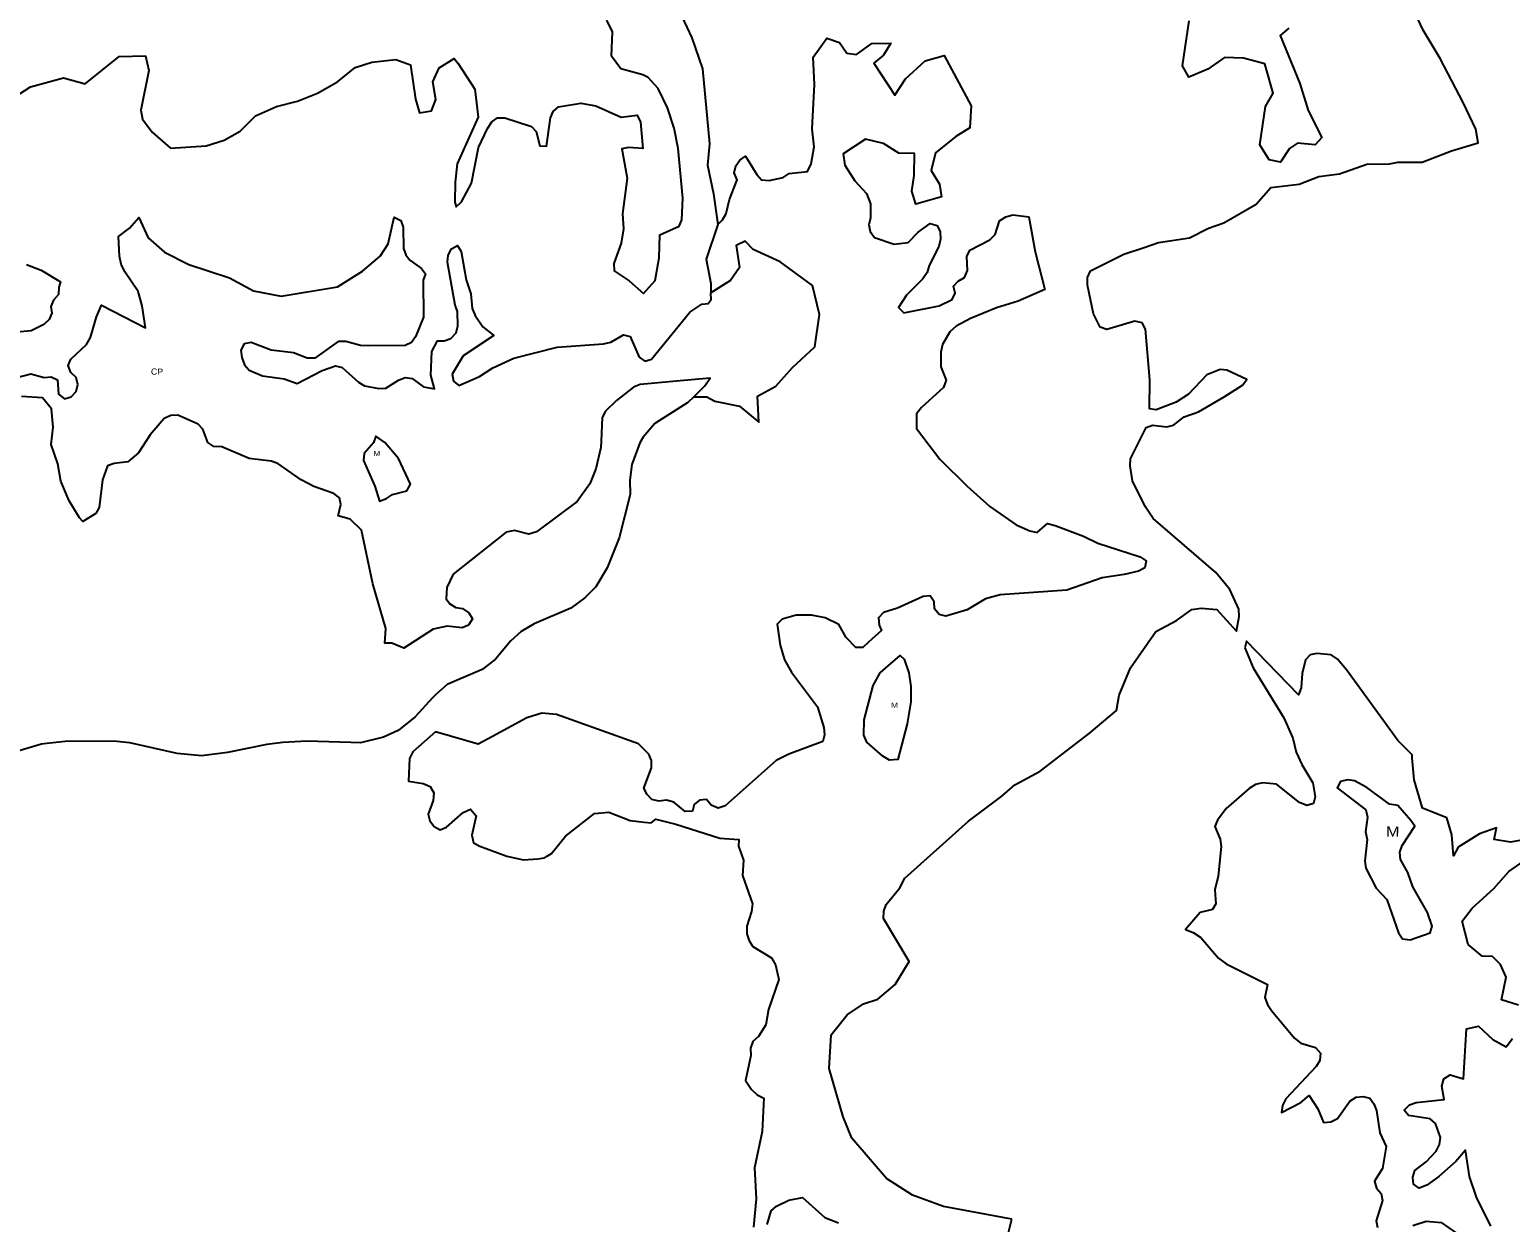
# Model space of a CAD drawing. Extents: x 713589 to 726391, y 7177764 to 7191819.
# Drawn here: x 722384 to 723901, y 7187990 to 7189212 of the extents above; entities that cross this region are included whole.
import ezdxf
from ezdxf.enums import TextEntityAlignment as Align

# ---------------------------------------------------------------- set-up
doc = ezdxf.new("R2010")
doc.units = 0
doc.header["$LTSCALE"] = 2.6
doc.layers.add('63', color=7, linetype='Continuous', lineweight=25)

msp = doc.modelspace()

# ---------------------------------------------------------------- linework, layer by layer
at = {"layer": '63'}
for points in [[(723389.91, 7187993.49), (723320.07, 7188006.34), (723288.31, 7188018.13), (723261.46, 7188035.17), (723226.1, 7188076.44), (723217.26, 7188098.38), (723202.86, 7188147.84), (723204.84, 7188182.22), (723221.22, 7188202.85), (723237.92, 7188213.98), (723252.66, 7188218.89), (723270.35, 7188233.95), (723284.89, 7188257.5), (723258.57, 7188301.42), (723258.9, 7188308.95), (723261.19, 7188315.83), (723275.28, 7188332.85), (723280.22, 7188342.71), (723345.7, 7188401.28), (723377.07, 7188424.8), (723379.77, 7188426.82), (723393.06, 7188438.48), (723419.07, 7188452.36), (723469.19, 7188490.99), (723497.03, 7188514.56), (723499.98, 7188530.28), (723511.45, 7188558.11), (723537.33, 7188595.44), (723558.62, 7188606.57), (723574.4, 7188617.83), (723583.84, 7188619.34), (723599.85, 7188618.12), (723619.83, 7188596.1), (723620, 7188595.93), (723622.98, 7188610.8), (723622.65, 7188618.39), (723613.41, 7188638.54), (723598.88, 7188655.72), (723534.82, 7188711.21), (723526.57, 7188723.43), (723513.7, 7188749.86), (723511.06, 7188765.05), (723511.39, 7188772.31), (723527.58, 7188804.34), (723534.18, 7188806.65), (723548.71, 7188805), (723555.65, 7188806.65), (723566.55, 7188815.23), (723581.08, 7188820.51), (723607.5, 7188835.7), (723626.33, 7188847.92), (723630.62, 7188853.53), (723610.15, 7188863.11), (723603.22, 7188863.77), (723589.68, 7188858.49), (723570.85, 7188838.68), (723558.3, 7188830.43), (723537.82, 7188822.51), (723530.88, 7188823.5), (723531.22, 7188853.22), (723526.94, 7188905.07), (723523.31, 7188911.67), (723516.04, 7188913.33), (723487.31, 7188904.75), (723480.37, 7188907.06), (723473.77, 7188920.93), (723467.5, 7188950.33), (723467.51, 7188957.92), (723470.48, 7188964.86), (723504.83, 7188982.02), (723525.64, 7188988.95), (723540.17, 7188993.9), (723571.87, 7188998.52), (723591.36, 7189008.42), (723607.21, 7189014.03), (723640.24, 7189033.18), (723655.44, 7189050.35), (723684.17, 7189053.65), (723704.31, 7189061.57), (723725.78, 7189064.2), (723753.52, 7189074.11), (723776.97, 7189074.43), (723785.56, 7189076.08), (723810.19, 7189076.2), (723840.38, 7189087.74), (723867.83, 7189095.87), (723865.48, 7189109.93), (723852.55, 7189136.7), (723828.72, 7189182.36), (723811.35, 7189211.55), (723795.36, 7189245.87)], [(723051.77, 7189225.54), (723061.97, 7189203.57), (723073.17, 7189171.66), (723080.1, 7189094.88), (723078.31, 7189072.96), (723084.37, 7189043.81), (723088.89, 7189012.51)], [(722980.78, 7189209.68), (722975, 7189221.69)], [(723673.6, 7189213.4), (723665.01, 7189205.89), (723685.06, 7189156.82), (723693.52, 7189129.03), (723707.48, 7189101.57), (723700.6, 7189094.06), (723682.78, 7189095.49), (723674.54, 7189090.04), (723665.24, 7189076.36), (723653.6, 7189078.46), (723644.06, 7189093.91), (723649.68, 7189133.3), (723657.61, 7189146.98), (723649.15, 7189176.82), (723627.23, 7189182.72), (723607.71, 7189183.48), (723590.87, 7189171.54), (723571.31, 7189163.39), (723564.84, 7189174.72), (723571.51, 7189220.95)], [(722351.49, 7189132.15), (722384.46, 7189153.29), (722418.41, 7189162.42), (722440.67, 7189156.51), (722475.37, 7189184.49), (722502.38, 7189185.01), (722505.71, 7189170.22), (722497.68, 7189129.47), (722499.21, 7189120.12), (722509.25, 7189106.82), (722528.04, 7189090.65), (722564.72, 7189092.92), (722582.9, 7189098.68), (722599.38, 7189107.87), (722615.2, 7189123.58), (722636.48, 7189133.1), (722658.08, 7189138.85), (722678.67, 7189147), (722699.27, 7189158.58), (722717.14, 7189173.25), (722734.3, 7189178.67), (722758.98, 7189181.33), (722774.04, 7189175.79), (722779.05, 7189140.82), (722783.12, 7189126.76), (722795.46, 7189128.77), (722799.95, 7189140.41), (722796.93, 7189158.58), (722803.15, 7189172.95), (722818.78, 7189182.41), (722822.7, 7189177.34), (722839.74, 7189150.89), (722843.07, 7189122.44), (722821.65, 7189074.32), (722819.57, 7189055.72), (722819.24, 7189035.09), (722820.79, 7189030.37), (722826.12, 7189035.41), (722836.27, 7189054.73), (722843.48, 7189091.08), (722852.66, 7189110.73), (722857.24, 7189117.61), (722863.14, 7189121.54), (722870.67, 7189121.53), (722897.85, 7189112.69), (722902.76, 7189107.44), (722906.36, 7189093.03), (722913.24, 7189092.71), (722917.5, 7189121.52), (722920.12, 7189128.07), (722925.69, 7189132.98), (722948.29, 7189136.58), (722963.68, 7189133.96), (722989.88, 7189122.16), (723006.12, 7189124.41), (723009.53, 7189117.25), (723011.86, 7189090.03), (722997.08, 7189091.05), (722990.53, 7189089.74), (722995.76, 7189059.94), (722991.17, 7189023.26), (722992.15, 7189007.87), (722989.85, 7188993.13), (722982.31, 7188972.5), (722982.64, 7188964.97), (722998.03, 7188954.49), (723012.63, 7188941.69), (723024.56, 7188955.14), (723028.82, 7188978.06), (723029.24, 7189001.68), (723049.13, 7189010.48), (723051.75, 7189017.03), (723052.74, 7189039.29), (723048.16, 7189090.06), (723043.91, 7189111.02), (723037.04, 7189131.98), (723027.55, 7189151.63), (723017.4, 7189162.77), (723012.02, 7189165.58), (722989.22, 7189171.96), (722979.67, 7189184.67), (722980.78, 7189209.68)], [(723088.89, 7189012.51), (723093.67, 7189017.02), (723097.27, 7189023.57), (723100.55, 7189037.97), (723108.42, 7189057.95), (723105.47, 7189065.16), (723107.11, 7189072.36), (723111.37, 7189078.25), (723117.26, 7189082.51), (723128.72, 7189063.51), (723133.63, 7189058.27), (723141.49, 7189057.29), (723155.57, 7189060.56), (723161.8, 7189064.49), (723180.55, 7189066.73), (723184.54, 7189074.64), (723187.34, 7189091.76), (723185.35, 7189110.28), (723187.91, 7189155.84), (723186.29, 7189183.6), (723200.41, 7189203.09), (723213.42, 7189198.93), (723220.92, 7189187.94), (723230.85, 7189186.53), (723246.65, 7189197.78), (723266.03, 7189198.14), (723258.36, 7189185.76), (723248.52, 7189177.59), (723270.11, 7189144.93), (723281.13, 7189161.68), (723301.07, 7189180.12), (723320.63, 7189185.53), (723348.2, 7189134.03), (723347.09, 7189111.42), (723332.67, 7189102.56), (723311.71, 7189085.85), (723307.19, 7189067.7), (723315.71, 7189053.62), (723318.06, 7189040.59), (723291.65, 7189033.15), (723287.59, 7189046.52), (723290.04, 7189062.62), (723290.12, 7189085.24), (723274.36, 7189085.29), (723258.63, 7189095.28), (723240.14, 7189099.8), (723217.13, 7189084.81), (723218.8, 7189073.15), (723229.03, 7189057.01), (723240.97, 7189043.95), (723245.11, 7189033.35), (723245.3, 7189019.28), (723243.33, 7189012.07), (723244.97, 7189005.19), (723249.22, 7188998.97), (723269.53, 7188992.09), (723283.61, 7188994.05), (723294.09, 7189004.53), (723306.21, 7189013.37), (723313.41, 7189011.4), (723316.69, 7189004.85), (723317.01, 7188997.32), (723315.05, 7188989.79), (723305.22, 7188970.47), (723303.25, 7188963.26), (723298.66, 7188956.71), (723281.96, 7188940.02), (723273.77, 7188927.25), (723279.34, 7188922), (723315.36, 7188929.2), (723328.79, 7188935.42), (723331.74, 7188941.97), (723330.1, 7188949.18), (723335.02, 7188954.41), (723341.57, 7188958.02), (723344.52, 7188965.22), (723343.86, 7188979.63), (723346.81, 7188986.18), (723367.45, 7188996.65), (723373.01, 7189002.22), (723377.28, 7189015.97), (723383.83, 7189020.23), (723391.03, 7189022.19), (723407.24, 7189020.17), (723413.93, 7188984.22), (723423.8, 7188945.82), (723396.58, 7188933.77), (723374.31, 7188926.9), (723347.45, 7188916.1), (723333.04, 7188908.24), (723326.49, 7188902.35), (723318.95, 7188889.57), (723317.32, 7188881.72), (723317.31, 7188866.65), (723322.55, 7188852.9)], [(722498.98, 7188929.09), (722494.89, 7188943.69), (722481.34, 7188964.03), (722477.41, 7188971.65), (722475.62, 7188979.82), (722474.85, 7188999.93), (722485.89, 7189008.68), (722495.61, 7189019.45), (722505.17, 7188998.8), (722521.87, 7188984.06), (722546.75, 7188971.29), (722588.34, 7188957.85), (722612.9, 7188944.42), (722641.39, 7188938.84), (722699.03, 7188948.33), (722724.58, 7188964.7), (722742.92, 7188979.76), (722751.11, 7188992.53), (722757.1, 7189019.97), (722763.89, 7189016.43), (722766.51, 7189009.55), (722766.83, 7188987.61), (722769.12, 7188981.39), (722773.38, 7188975.82), (722785.16, 7188967.3), (722789.42, 7188961.74), (722786.8, 7188955.19), (722787.12, 7188917.53), (722778.93, 7188897.22), (722775, 7188891.33), (722768.45, 7188888.38), (722730.78, 7188888.06), (722722.6, 7188888.39), (722707.53, 7188892.65), (722699.67, 7188892.33), (722675.76, 7188875.3), (722667.9, 7188875.31), (722654.15, 7188880.88), (722631.23, 7188883.5), (722610.6, 7188891.36), (722603.39, 7188890.06), (722600.11, 7188883.51), (722601.1, 7188875.97), (722603.71, 7188868.44), (722608.63, 7188863.2), (722622.38, 7188857.3), (722644.32, 7188854.35), (722657.75, 7188849.44), (722683.29, 7188862.86), (722697.05, 7188867.44), (722703.93, 7188865.8), (722720.62, 7188850.73), (722726.85, 7188847.13), (722741.58, 7188844.51), (722748.79, 7188844.83), (722761.56, 7188853.02), (722768.44, 7188855.63), (722775.64, 7188854.65), (722787.1, 7188846.13), (722798.52, 7188844.12), (722794.87, 7188858.03), (722795.87, 7188882.1), (722801.46, 7188893.22), (722808.4, 7188893.29), (722815.28, 7188895.58), (722820.52, 7188901.47), (722822.49, 7188908.68), (722822.16, 7188923.09), (722819.54, 7188929.64), (722811.69, 7188973.85), (722812.35, 7188981.05), (722815.95, 7188987.27), (722822.18, 7188990.88), (722825.78, 7188984.65), (722831.01, 7188955.51), (722835.59, 7188941.42), (722837.23, 7188926.36), (722840.17, 7188919.15), (722848.03, 7188907.36), (722859.16, 7188898.52), (722827.72, 7188877.89), (722816.58, 7188858.9), (722817.89, 7188852.02), (722823.45, 7188847.44), (722844.74, 7188856.6), (722858.17, 7188865.44), (722879.79, 7188875.59), (722924, 7188886.71), (722971.49, 7188889.98), (722979.02, 7188891.94), (722992.12, 7188899.47), (722999, 7188897.5), (723008.16, 7188876.54), (723014.06, 7188872.28), (723020.94, 7188874.25), (723059.92, 7188922.38), (723072.36, 7188930.89), (723078.92, 7188931.27), (723081.86, 7188935.47), (723081.73, 7188942.3)], [(723088.89, 7189012.51), (723076.96, 7188976.74), (723081.54, 7188951.85), (723081.73, 7188942.3)], [(723064.05, 7188835.88), (723077.58, 7188835.92), (723085.77, 7188831.33), (723110.99, 7188826.41), (723130.84, 7188809.79), (723129.48, 7188836.61), (723148.32, 7188846.71), (723165.36, 7188865.7), (723188.29, 7188886.98), (723192.88, 7188920.06), (723185.68, 7188949.86), (723175.38, 7188957.41), (723152.61, 7188974.1), (723125.1, 7188986.88), (723116.92, 7188995.4), (723107.42, 7188990.81), (723111.02, 7188968.22), (723101.84, 7188955.12), (723081.73, 7188942.3)], [(722380.53, 7188971.38), (722395.62, 7188965.6), (722415.43, 7188953.78), (722413.46, 7188948.06), (722413.13, 7188940.53), (722408.22, 7188934.96), (722405.27, 7188928.42), (722406.58, 7188921.54), (722403.63, 7188914.99), (722398.39, 7188909.75), (722385.29, 7188903.53), (722370.55, 7188901.9)], [(722370.54, 7188855.72), (722384.95, 7188859.32), (722398.7, 7188855.71), (722405.91, 7188856.37), (722412.13, 7188853.09), (722413.44, 7188838.68), (722419.33, 7188833.77), (722426.21, 7188835.73), (722431.45, 7188841.3), (722433.09, 7188848.5), (722431.45, 7188855.71), (722425.89, 7188860.62), (722423.27, 7188867.83), (722425.89, 7188874.38), (722441.94, 7188889.44), (722446.2, 7188896.64), (722452.1, 7188917.6), (722457.3, 7188929.62), (722502.44, 7188906.65), (722498.98, 7188929.09)], [(723064.05, 7188835.88), (723075.26, 7188846.76), (723081.01, 7188854.98), (723046.41, 7188851.81), (723009.14, 7188848.38), (723002.26, 7188845.76), (722984.9, 7188832.01), (722973.77, 7188821.2), (722970.16, 7188814.66), (722969.13, 7188790.34), (722968.85, 7188783.87), (722963.93, 7188761.93), (722957.7, 7188746.54), (722944.6, 7188728.53), (722903, 7188697.43), (722895.14, 7188695.14), (722880.41, 7188698.74), (722871.89, 7188697.11), (722817.52, 7188654.22), (722811.29, 7188640.47), (722810.49, 7188629.02), (722814.24, 7188623.76), (722820.46, 7188620.16), (722827.34, 7188618.85), (722833.56, 7188614.59), (722837.49, 7188608.37), (722833.23, 7188601.82), (722826.68, 7188599.2), (722811.61, 7188600.84), (722797.2, 7188597.89), (722767.07, 7188578.25), (722754.63, 7188583.49), (722747.66, 7188583.58), (722748.73, 7188598.56), (722735.32, 7188644.41), (722723.54, 7188699.1), (722712.24, 7188710.4), (722699.8, 7188713.81), (722702.59, 7188725.64), (722701.28, 7188732.51), (722695.38, 7188736.77), (722674.75, 7188743.98), (722661.98, 7188750.86), (722638.08, 7188767.57), (722631.2, 7188769.86), (722608.61, 7188772.81), (722580.77, 7188784.61), (722572.58, 7188784.94), (722566.36, 7188789.2), (722561.13, 7188802.63), (722556.22, 7188807.87), (722535.59, 7188817.04), (722528.38, 7188816.72), (722521.5, 7188813.77), (722507.09, 7188796.74), (722495.3, 7188778.41), (722484.16, 7188769.24), (722470.4, 7188767.6), (722463.53, 7188764.99), (722458.28, 7188750.9), (722455, 7188722.41), (722451.4, 7188716.19), (722438.19, 7188708.27), (722434.7, 7188711.94), (722424.22, 7188729.3), (722415.71, 7188749.6), (722412.44, 7188767.29), (722405.89, 7188786.94), (722407.86, 7188804.62), (722406.23, 7188823.62), (722396.73, 7188834.76), (722375.45, 7188836.07)], [(723322.55, 7188852.9), (723319.93, 7188845.36), (723297.33, 7188824.74), (723292.41, 7188818.52), (723292.41, 7188803.45), (723316.31, 7188772.01), (723344.14, 7188744.16), (723367.39, 7188723.53), (723394.24, 7188704.85), (723408.32, 7188698.63), (723415.85, 7188696.99), (723426.66, 7188706.16), (723434.19, 7188703.86), (723463.34, 7188693.05), (723478.07, 7188685.84), (723521.3, 7188672.08), (723527.52, 7188667.82), (723526.21, 7188660.62), (723519.66, 7188657.34), (723504.92, 7188653.74), (723482.65, 7188650.47), (723446.29, 7188637.71), (723377.85, 7188633.14), (723363.11, 7188628.88), (723344.11, 7188617.75), (723322.5, 7188611.21), (723315.62, 7188612.85), (723310.71, 7188618.74), (723310.38, 7188625.95), (723306.45, 7188631.84), (723299.25, 7188631.19), (723272.72, 7188619.41), (723258.31, 7188614.82), (723253.4, 7188609.59), (723254.05, 7188602.05), (723256.32, 7188596.58), (723243.26, 7188584.57), (723237.34, 7188579.13), (723230.14, 7188579.13), (723220.32, 7188589.29), (723212.79, 7188602.72), (723198.71, 7188609.27), (723184.62, 7188612.22), (723168.91, 7188612.22), (723154.82, 7188607.97), (723149.58, 7188603.06), (723152.52, 7188581.44), (723157.11, 7188566.38), (723164.31, 7188553.93), (723190.83, 7188518.23), (723197.37, 7188496.94), (723198.03, 7188489.74), (723196.39, 7188482.86), (723161.34, 7188469.77), (723148.57, 7188463.22), (723096.16, 7188416.73), (723088.96, 7188414.44), (723082.08, 7188417.71), (723077.17, 7188423.28), (723069.96, 7188422.63), (723064.39, 7188418.37), (723062.76, 7188411.5), (723055.22, 7188411.17), (723043.76, 7188420.67), (723036.23, 7188422.64), (723028.37, 7188421.66), (723021.17, 7188423.29), (723016.26, 7188428.54), (723012.98, 7188435.09), (723020.85, 7188455.72), (723020.85, 7188463.25), (723017.9, 7188469.8), (723007.42, 7188480.28), (722923.59, 7188510.43), (722908.53, 7188511.74), (722893.14, 7188507.16), (722858.07, 7188487.96), (722843.39, 7188479.93), (722799.63, 7188492.74), (722776.22, 7188472.14), (722772.94, 7188465.27), (722771.95, 7188442.02), (722787.02, 7188439.72), (722794.22, 7188436.77), (722797.82, 7188430.22), (722797.16, 7188422.36), (722791.92, 7188408.28), (722793.56, 7188401.4), (722798.14, 7188395.83), (722804.36, 7188392.23), (722810.91, 7188394.85), (722827.95, 7188409.91), (722835.48, 7188413.51), (722841.01, 7188406.68)], [(723064.05, 7188835.88), (723057.97, 7188829.98), (723046.6, 7188822.85), (723024.33, 7188808.56), (723012.12, 7188794.63), (723008.83, 7188788.78), (723000.5, 7188766.36), (722998.5, 7188750.46), (722998.85, 7188735.66), (722987.53, 7188691.37), (722975.46, 7188660.82), (722963.65, 7188641.29), (722952.53, 7188629.79), (722938.03, 7188619.37), (722900.46, 7188603.29), (722887.35, 7188595.47), (722876.78, 7188585.9), (722860.83, 7188566.97), (722847.48, 7188556.51), (722811.4, 7188541.02), (722799.84, 7188530.78), (722796.28, 7188527.62), (722778.65, 7188508.19), (722761.11, 7188494.19), (722746.16, 7188487.07), (722722.84, 7188481.39), (722712.83, 7188481.73), (722667.68, 7188483.25), (722643.06, 7188481.81), (722626.77, 7188479.82), (722586.55, 7188471.36), (722559.7, 7188468.12), (722534.93, 7188470.62), (722486.25, 7188481.25), (722469.76, 7188483.19), (722420.08, 7188482.7), (722401.3, 7188480.73), (722395.91, 7188480.17), (722371.59, 7188472.75)], [(723628.69, 7188578.72), (723637.2, 7188558.09), (723668.63, 7188506.99), (723677.8, 7188486.03), (723681.4, 7188471.95), (723686.96, 7188459.18), (723698.42, 7188440.51), (723700.71, 7188426.1), (723699.07, 7188419.22), (723692.19, 7188417.26), (723684.66, 7188420.2), (723661.08, 7188439.2), (723646.67, 7188440.52), (723639.47, 7188438.55), (723633.25, 7188434.62), (723609.66, 7188414), (723600.82, 7188402.21), (723597.87, 7188395.66), (723603.43, 7188382.56), (723604.41, 7188375.36), (723601.46, 7188344.9), (723597.86, 7188330.82), (723598.83, 7188316.41), (723595.56, 7188310.84), (723582.95, 7188307.76), (723567.9, 7188290.08), (723575.88, 7188287.23), (723583.74, 7188281.95), (723601.83, 7188260.97), (723609.47, 7188255.08), (723651.72, 7188233.85), (723649.25, 7188220.44), (723651.87, 7188213.24), (723656.12, 7188207.34), (723679.69, 7188178.85), (723685.92, 7188173.6), (723700.98, 7188169.34), (723706.22, 7188163.45), (723705.56, 7188155.92), (723701.63, 7188149.69), (723670.51, 7188116.63), (723667.24, 7188109.75), (723666.37, 7188102.61), (723686.14, 7188112.93), (723694.72, 7188120.22), (723703.59, 7188106.47), (723709.15, 7188092.38), (723716.68, 7188093.04), (723723.56, 7188096.64), (723736.34, 7188114.32), (723742.56, 7188118.57), (723749.76, 7188119.23), (723756.64, 7188117.26), (723760.9, 7188111.69), (723763.52, 7188104.82), (723767.11, 7188081.89), (723773.33, 7188067.81), (723769.73, 7188045.21), (723761.54, 7188032.44), (723763.5, 7188025.24), (723768.41, 7188019.67), (723769.72, 7188012.46), (723763.16, 7187991.83), (723764.47, 7187984.95)], [(723931.05, 7188385.17), (723900.66, 7188379.57), (723884.15, 7188382.54), (723886.59, 7188394.34), (723868.96, 7188388.16), (723847.16, 7188374.62), (723842.59, 7188365.52), (723840.89, 7188387.18), (723835.61, 7188404.68), (723810.84, 7188414.59), (723802.26, 7188443.66), (723800.24, 7188466.04), (723800.12, 7188469.22), (723785.43, 7188483.62), (723732.94, 7188556.28), (723723.69, 7188567.18), (723717.09, 7188571.48), (723702.56, 7188572.8), (723695.62, 7188571.48), (723690.67, 7188566.53), (723687.36, 7188552.33), (723686.37, 7188537.8), (723683.8, 7188530.73), (723630.33, 7188585.37), (723628.69, 7188578.72)], [(722841.01, 7188406.68), (722836.78, 7188386.98), (722838.42, 7188378.8), (722844.97, 7188375.52), (722872.47, 7188365.36), (722889.83, 7188361.43), (722904.24, 7188362.41), (722911.12, 7188363.72), (722913.28, 7188364.99), (722918.32, 7188367.97), (722932.74, 7188385.65), (722962.54, 7188408.9), (722976.95, 7188410.53), (722998.89, 7188402.01), (723013.3, 7188400.04), (723020.51, 7188399.39), (723025.13, 7188403.26), (723045.72, 7188398.07), (723090.76, 7188383.59), (723110.32, 7188382.43), (723109.91, 7188375.46), (723115.14, 7188361.05), (723114.16, 7188345.66), (723124.3, 7188316.51), (723123.32, 7188308.65), (723118.4, 7188293.59), (723118.4, 7188285.73), (723120.69, 7188278.52), (723124.62, 7188272.63), (723143.61, 7188261.16), (723147.87, 7188253.96), (723151.14, 7188238.89), (723140.65, 7188208.11), (723138.03, 7188192.39), (723130.5, 7188180.6), (723124.6, 7188175.36), (723122.31, 7188168.49), (723122.63, 7188161.28), (723117.26, 7188135.4), (723123.08, 7188126.38), (723129.21, 7188120.95), (723135.86, 7188117.47), (723134.12, 7188083.3), (723126.24, 7188046.13), (723128.18, 7188014.19), (723125.18, 7187985.3)], [(723908.88, 7188212.79), (723891.55, 7188217.99), (723896.28, 7188241.22), (723890.73, 7188254.41), (723882.48, 7188262.66), (723871.91, 7188263), (723857.35, 7188274.83), (723851.37, 7188298.89), (723861.68, 7188311.88), (723883.81, 7188332.02), (723899.01, 7188349.52), (723918.16, 7188363.05)], [(723865.98, 7188016.07), (723858.78, 7188037.03), (723854.77, 7188064.25), (723844.72, 7188052.4), (723827.36, 7188037.01), (723815.24, 7188028.17), (723807.38, 7188025.23), (723801.49, 7188029.16), (723800.84, 7188036.36), (723802.8, 7188043.24), (723814.27, 7188052.08), (723824.75, 7188063.21), (723828.02, 7188070.09), (723829.01, 7188077.29), (723824.1, 7188091.38), (723818.53, 7188096.29), (723796.26, 7188099.57), (723792.01, 7188105.14), (723797.25, 7188110.7), (723804.13, 7188112.99), (723832.95, 7188115.94), (723830.33, 7188129.69), (723832.62, 7188137.22), (723839.17, 7188141.15), (723852.59, 7188137.22), (723855.8, 7188188.38), (723867.96, 7188191.21), (723882.79, 7188177.46), (723896.33, 7188169.86), (723902.93, 7188178.45)], [(723139.3, 7187988.04), (723143.23, 7188002.12), (723148.8, 7188006.7), (723161.57, 7188012.92), (723175.65, 7188015.54), (723198.25, 7187995.23), (723212.33, 7187989.66)], [(723880.71, 7187986.26), (723865.98, 7188016.07)], [(723385.89, 7187977.18), (723389.91, 7187993.49)], [(723800.82, 7187986.91), (723814.58, 7187991.49), (723829.64, 7187990.18), (723853.22, 7187973.8)]]:
    msp.add_lwpolyline(points, dxfattribs=at)
for points in [[(722755.31, 7188735.78), (722770.05, 7188739.7), (722773.98, 7188746.25), (722761.54, 7188772.78), (722747.46, 7188789.16), (722738.52, 7188795.45), (722736, 7188788.83), (722726.5, 7188777.7), (722725.85, 7188770.5), (722737.3, 7188744.29), (722742.21, 7188728.9), (722749.42, 7188731.52)], [(723247.81, 7188540.16), (723255.02, 7188553.26), (723263.23, 7188560.28), (723275.63, 7188570.89), (723279.59, 7188567.01), (723284.5, 7188553.25), (723286.46, 7188539.17), (723286.45, 7188528.97), (723286.45, 7188523.45), (723282.85, 7188500.85), (723273.01, 7188464.18), (723264.5, 7188463.52), (723257.95, 7188467.78), (723241.25, 7188482.2), (723238.31, 7188489.4), (723238.64, 7188504.79)], [(723774.04, 7188320.96), (723786.15, 7188286.89), (723790.08, 7188280.67), (723797.94, 7188279.69), (723818.57, 7188286.89), (723820.54, 7188293.76), (723815.96, 7188307.52), (723800.9, 7188334.05), (723795.66, 7188348.46), (723788.13, 7188361.89), (723787.48, 7188369.42), (723789.77, 7188376.3), (723802.82, 7188395.89), (723798.6, 7188401.86), (723785.4, 7188417.34), (723777.01, 7188418.55), (723753.76, 7188435.58), (723740.99, 7188442.46), (723733.79, 7188443.45), (723726.58, 7188441.81), (723723.31, 7188435.26), (723752.78, 7188412.66), (723754.41, 7188405.12), (723752.12, 7188390.39), (723754.08, 7188382.53), (723751.45, 7188360.26), (723752.76, 7188353.05), (723763.24, 7188332.42)]]:
    msp.add_lwpolyline(points, close=True, dxfattribs=at)

# ---------------------------------------------------------------- texts
for s, height, width, p in [('CP', 6.4, 1.05, (722514.18, 7188858.41)), ('M', 5.2, 1.2, (722739.33, 7188775.24)), ('M', 5.2, 1.2, (723269.73, 7188517.31)), ('M', 10.4, 1.2, (723780.1, 7188385.36))]:
    msp.add_text(s, height=height, rotation=359.062, dxfattribs=dict(at, width=width)).set_placement(p, align=Align.CENTER)

doc.saveas('drawing.dxf')
